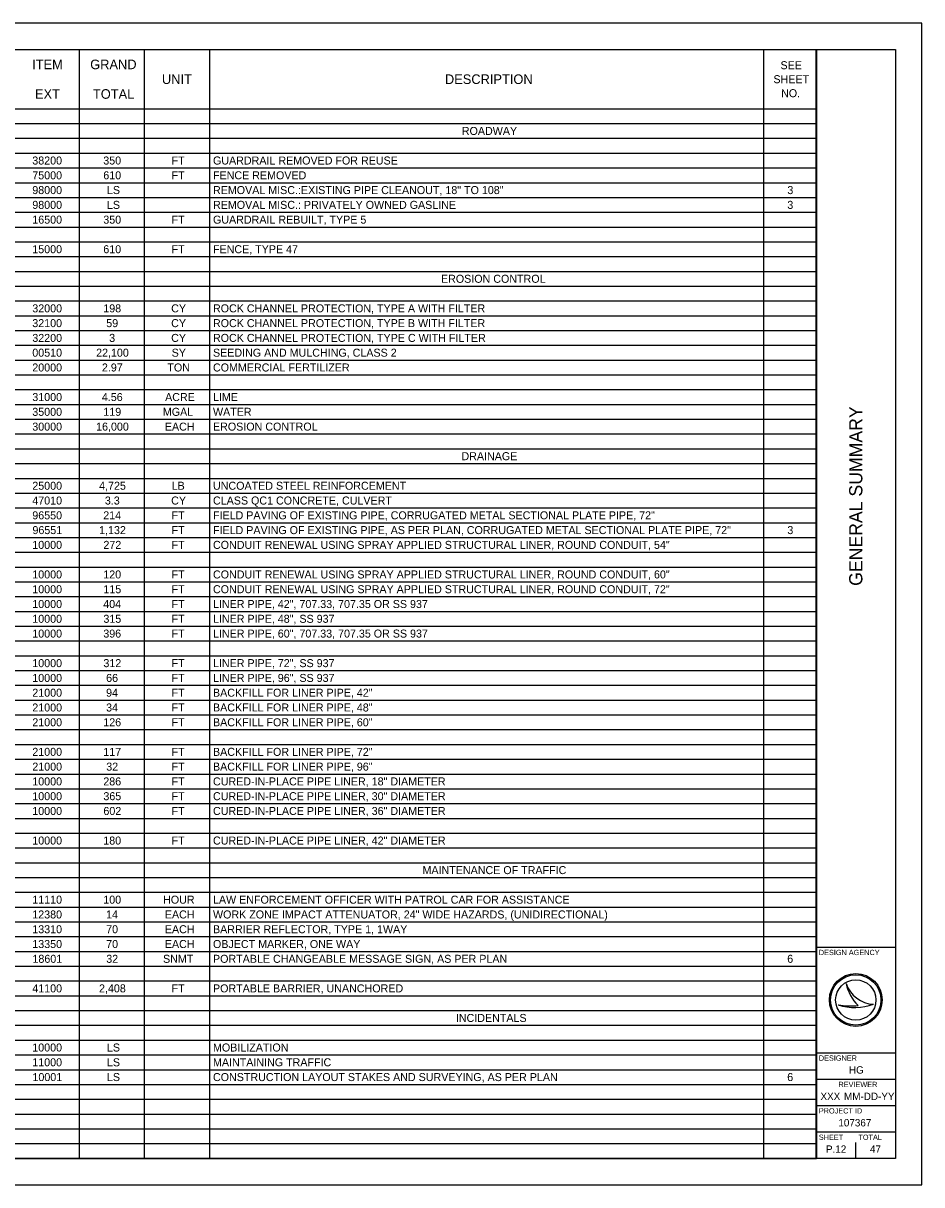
# Model space of a CAD drawing. Extents: x 0 to 34, y 0 to 22.
# Drawn here: x 16.98 to 34, y 0 to 22 of the extents above; entities that cross this region are included whole.
import ezdxf

# ---------------------------------------------------------------- set-up
doc = ezdxf.new("R2010")
doc.units = 0
for name, color, linetype in [('Default', 7, 'Continuous'), ('SH_Border', 7, 'Continuous'), ('SH_Cut_Line', 7, 'Continuous'), ('SH_Data', 7, 'Continuous')]:
    doc.layers.add(name, color=color, linetype=linetype)

msp = doc.modelspace()

# ---------------------------------------------------------------- linework, layer by layer
at = {"layer": 'Default'}
for p, q in [((1.5, 21.5), (32.004, 21.5)), ((18.036, 21.5), (18.036, 0.5)), ((19.272, 21.5), (19.272, 0.5)), ((20.507, 21.5), (20.507, 0.5)), ((30.999, 21.5), (30.999, 0.5)), ((32.004, 21.5), (32.004, 0.5)), ((1.5, 20.38), (32.004, 20.38)), ((1.5, 20.1), (32.004, 20.1)), ((1.5, 19.82), (32.004, 19.82)), ((1.5, 19.54), (32.004, 19.54)), ((1.5, 19.26), (32.004, 19.26)), ((1.5, 18.98), (32.004, 18.98)), ((1.5, 18.7), (32.004, 18.7)), ((1.5, 18.42), (32.004, 18.42)), ((1.5, 18.14), (32.004, 18.14)), ((1.5, 17.86), (32.004, 17.86)), ((1.5, 17.58), (32.004, 17.58)), ((1.5, 17.3), (32.004, 17.3)), ((1.5, 17.02), (32.004, 17.02)), ((1.5, 16.74), (32.004, 16.74)), ((1.5, 16.46), (32.004, 16.46)), ((1.5, 16.18), (32.004, 16.18)), ((1.5, 15.9), (32.004, 15.9)), ((1.5, 15.62), (32.004, 15.62)), ((1.5, 15.34), (32.004, 15.34)), ((1.5, 15.06), (32.004, 15.06)), ((1.5, 14.78), (32.004, 14.78)), ((1.5, 14.5), (32.004, 14.5)), ((1.5, 14.22), (32.004, 14.22)), ((1.5, 13.94), (32.004, 13.94)), ((1.5, 13.66), (32.004, 13.66)), ((1.5, 13.38), (32.004, 13.38)), ((1.5, 13.1), (32.004, 13.1)), ((1.5, 12.82), (32.004, 12.82)), ((1.5, 12.54), (32.004, 12.54)), ((1.5, 12.26), (32.004, 12.26)), ((1.5, 11.98), (32.004, 11.98)), ((1.5, 11.7), (32.004, 11.7)), ((1.5, 11.42), (32.004, 11.42)), ((1.5, 11.14), (32.004, 11.14)), ((1.5, 10.86), (32.004, 10.86)), ((1.5, 10.58), (32.004, 10.58)), ((1.5, 10.3), (32.004, 10.3)), ((1.5, 10.02), (32.004, 10.02)), ((1.5, 9.74), (32.004, 9.74)), ((1.5, 9.46), (32.004, 9.46)), ((1.5, 9.18), (32.004, 9.18)), ((1.5, 8.9), (32.004, 8.9)), ((1.5, 8.62), (32.004, 8.62)), ((1.5, 8.34), (32.004, 8.34)), ((1.5, 8.06), (32.004, 8.06)), ((1.5, 7.78), (32.004, 7.78)), ((1.5, 7.5), (32.004, 7.5)), ((1.5, 7.22), (32.004, 7.22)), ((1.5, 6.94), (32.004, 6.94)), ((1.5, 6.66), (32.004, 6.66)), ((1.5, 6.38), (32.004, 6.38)), ((1.5, 6.1), (32.004, 6.1)), ((1.5, 5.82), (32.004, 5.82)), ((1.5, 5.54), (32.004, 5.54)), ((1.5, 5.26), (32.004, 5.26)), ((1.5, 4.98), (32.004, 4.98)), ((1.5, 4.7), (32.004, 4.7)), ((1.5, 4.42), (32.004, 4.42)), ((1.5, 4.14), (32.004, 4.14)), ((1.5, 3.86), (32.004, 3.86)), ((1.5, 3.58), (32.004, 3.58)), ((1.5, 3.3), (32.004, 3.3)), ((1.5, 3.02), (32.004, 3.02)), ((1.5, 2.74), (32.004, 2.74)), ((1.5, 2.46), (32.004, 2.46)), ((1.5, 2.18), (32.004, 2.18)), ((1.5, 1.9), (32.004, 1.9)), ((1.5, 1.62), (32.004, 1.62)), ((1.5, 1.34), (32.004, 1.34)), ((1.5, 1.06), (32.004, 1.06)), ((1.5, 0.78), (32.004, 0.78)), ((1.5, 0.5), (32.004, 0.5))]:
    msp.add_line(p, q, dxfattribs=at)
at = {"layer": 'SH_Border'}
for p, q in [((32, 0.5), (32, 21.5)), ((32, 4.5), (33.5, 4.5)), ((32, 2.5), (33.5, 2.5)), ((32, 2), (33.5, 2)), ((32, 1.5), (33.5, 1.5)), ((32, 1), (33.5, 1))]:
    msp.add_line(p, q, dxfattribs=at)
msp.add_lwpolyline([(1.5, 21.5), (33.5, 21.5), (33.5, 0.5), (1.5, 0.5)], close=True, dxfattribs=at)
at = {"layer": 'SH_Cut_Line'}
msp.add_lwpolyline([(0, 0), (34, 0), (34, 22), (0, 22)], close=True, dxfattribs=at)
at = {"layer": 'SH_Data'}
for p, q in [((32.567, 3.81), (32.567, 3.81)), ((32.417, 3.41), (32.417, 3.41)), ((32.75, 3.5), (32.75, 3.5)), ((33.087, 3.419), (33.087, 3.419)), ((32.375, 0.675), (32.375, 0.675)), ((32.75, 0.5), (32.75, 0.8))]:
    msp.add_line(p, q, dxfattribs=at)
for radius in [0.5, 0.477, 0.477, 0.382]:
    msp.add_circle((32.75, 3.5), radius, dxfattribs=at)
for centre, radius, start, end in [((33.116, 3.998), 0.58, 198.9257, 198.9319), ((33.347, 3.97), 0.796, 191.6379, 191.6421), ((33.116, 3.998), 0.58, 198.9319, 267.1657), ((33.347, 3.97), 0.796, 191.6421, 226.0947), ((32.739, 4.37), 1.013, 251.4576, 290.0832), ((32.648, 4.654), 1.266, 259.4964, 259.4995), ((32.739, 4.37), 1.013, 251.4527, 251.4576), ((32.648, 4.654), 1.266, 259.4995, 276.6672)]:
    msp.add_arc(centre, radius, start, end, dxfattribs=at)

# ---------------------------------------------------------------- texts
at = {"layer": 'Default'}
for s, height, p in [('ITEM', 0.1818, (17.147, 21.129)), ('GRAND', 0.1818, (18.247, 21.129)), ('SEE ', 0.1515, (31.324, 21.129)), ('UNIT', 0.1818, (19.606, 20.849)), ('DESCRIPTION', 0.18184, (24.967, 20.849)), ('SHEET ', 0.1515, (31.19, 20.864)), ('EXT', 0.1818, (17.201, 20.569)), ('TOTAL', 0.1818, (18.299, 20.569)), ('NO.', 0.1515, (31.335, 20.599)), ('ROADWAY', 0.1515, (25.287, 19.884)), ('38200', 0.1515, (17.15, 19.324)), ('350', 0.1515, (18.495, 19.324)), ('FT', 0.1515, (19.789, 19.324)), ('GUARDRAIL REMOVED FOR REUSE', 0.15153, (20.573, 19.324)), ('75000', 0.1515, (17.15, 19.044)), ('610', 0.1515, (18.495, 19.044)), ('FT', 0.1515, (19.789, 19.044)), ('FENCE REMOVED', 0.15153, (20.573, 19.044)), ('98000', 0.1515, (17.15, 18.764)), ('LS', 0.1515, (18.564, 18.764)), ('REMOVAL MISC.:EXISTING PIPE CLEANOUT, 18" TO 108"', 0.15153, (20.573, 18.764)), ('3', 0.152, (31.453, 18.764)), ('98000', 0.1515, (17.15, 18.484)), ('LS', 0.1515, (18.564, 18.484)), ('REMOVAL MISC.: PRIVATELY OWNED GASLINE', 0.15153, (20.573, 18.484)), ('3', 0.152, (31.453, 18.484)), ('16500', 0.1515, (17.15, 18.204)), ('350', 0.1515, (18.495, 18.204)), ('FT', 0.1515, (19.789, 18.204)), ('GUARDRAIL REBUILT, TYPE 5', 0.15153, (20.573, 18.204)), ('15000', 0.1515, (17.15, 17.644)), ('610', 0.1515, (18.495, 17.644)), ('FT', 0.1515, (19.789, 17.644)), ('FENCE, TYPE 47', 0.15153, (20.573, 17.644)), ('EROSION CONTROL', 0.15153, (24.892, 17.084)), ('32000', 0.1515, (17.15, 16.524)), ('198', 0.1515, (18.495, 16.524)), ('CY', 0.1515, (19.781, 16.524)), ('ROCK CHANNEL PROTECTION, TYPE A WITH FILTER', 0.15153, (20.573, 16.524)), ('32100', 0.1515, (17.15, 16.244)), ('59', 0.1515, (18.551, 16.244)), ('CY', 0.1515, (19.781, 16.244)), ('ROCK CHANNEL PROTECTION, TYPE B WITH FILTER', 0.15153, (20.573, 16.244)), ('32200', 0.1515, (17.15, 15.964)), ('3', 0.152, (18.606, 15.964)), ('CY', 0.1515, (19.781, 15.964)), ('ROCK CHANNEL PROTECTION, TYPE C WITH FILTER', 0.15153, (20.573, 15.964)), ('00510', 0.1515, (17.15, 15.684)), ('22,100', 0.1515, (18.359, 15.684)), ('SY', 0.1515, (19.79, 15.684)), ('SEEDING AND MULCHING, CLASS 2', 0.15153, (20.573, 15.684)), ('20000', 0.1515, (17.15, 15.404)), ('2.97', 0.1515, (18.469, 15.404)), ('TON', 0.1515, (19.709, 15.404)), ('COMMERCIAL FERTILIZER', 0.15153, (20.573, 15.404)), ('31000', 0.1515, (17.15, 14.844)), ('4.56', 0.1515, (18.468, 14.844)), ('ACRE', 0.1515, (19.666, 14.844)), ('LIME', 0.1515, (20.573, 14.844)), ('35000', 0.1515, (17.15, 14.564)), ('119', 0.1515, (18.496, 14.564)), ('MGAL', 0.1515, (19.623, 14.564)), ('WATER', 0.1515, (20.573, 14.564)), ('30000', 0.1515, (17.15, 14.284)), ('16,000', 0.1515, (18.359, 14.284)), ('EACH', 0.1515, (19.661, 14.284)), ('EROSION CONTROL', 0.15153, (20.573, 14.284)), ('DRAINAGE', 0.1515, (25.28, 13.724)), ('25000', 0.1515, (17.15, 13.164)), ('4,725', 0.1515, (18.416, 13.164)), ('LB', 0.1515, (19.79, 13.164)), ('UNCOATED STEEL REINFORCEMENT', 0.15153, (20.573, 13.164)), ('47010', 0.1515, (17.15, 12.884)), ('3.3', 0.1515, (18.525, 12.884)), ('CY', 0.1515, (19.781, 12.884)), ('CLASS QC1 CONCRETE, CULVERT', 0.15153, (20.573, 12.884)), ('96550', 0.1515, (17.15, 12.604)), ('214', 0.1515, (18.494, 12.604)), ('FT', 0.1515, (19.789, 12.604)), ('FIELD PAVING OF EXISTING PIPE, CORRUGATED METAL SECTIONAL PLATE PIPE, 72"', 0.15153, (20.573, 12.604)), ('96551', 0.1515, (17.153, 12.324)), ('1,132', 0.1515, (18.416, 12.324)), ('FT', 0.1515, (19.789, 12.324)), ('FIELD PAVING OF EXISTING PIPE, AS PER PLAN, CORRUGATED METAL SECTIONAL PLATE PIPE, 72"', 0.15153, (20.573, 12.324)), ('3', 0.152, (31.453, 12.324)), ('10000', 0.1515, (17.15, 12.044)), ('272', 0.1515, (18.497, 12.044)), ('FT', 0.1515, (19.789, 12.044)), ('CONDUIT RENEWAL USING SPRAY APPLIED STRUCTURAL LINER, ROUND CONDUIT, 54"', 0.15153, (20.573, 12.044)), ('10000', 0.1515, (17.15, 11.484)), ('120', 0.1515, (18.495, 11.484)), ('FT', 0.1515, (19.789, 11.484)), ('CONDUIT RENEWAL USING SPRAY APPLIED STRUCTURAL LINER, ROUND CONDUIT, 60"', 0.15153, (20.573, 11.484)), ('10000', 0.1515, (17.15, 11.204)), ('115', 0.1515, (18.497, 11.204)), ('FT', 0.1515, (19.789, 11.204)), ('CONDUIT RENEWAL USING SPRAY APPLIED STRUCTURAL LINER, ROUND CONDUIT, 72"', 0.15153, (20.573, 11.204)), ('10000', 0.1515, (17.15, 10.924)), ('404', 0.1515, (18.494, 10.924)), ('FT', 0.1515, (19.789, 10.924)), ('LINER PIPE, 42", 707.33, 707.35 OR SS 937', 0.15153, (20.573, 10.924)), ('10000', 0.1515, (17.15, 10.644)), ('315', 0.1515, (18.497, 10.644)), ('FT', 0.1515, (19.789, 10.644)), ('LINER PIPE, 48", SS 937', 0.15153, (20.573, 10.644)), ('10000', 0.1515, (17.15, 10.364)), ('396', 0.1515, (18.495, 10.364)), ('FT', 0.1515, (19.789, 10.364)), ('LINER PIPE, 60", 707.33, 707.35 OR SS 937', 0.15153, (20.573, 10.364)), ('10000', 0.1515, (17.15, 9.804)), ('312', 0.1515, (18.497, 9.804)), ('FT', 0.1515, (19.789, 9.804)), ('LINER PIPE, 72", SS 937', 0.15153, (20.573, 9.804)), ('10000', 0.1515, (17.15, 9.524)), ('66', 0.1515, (18.549, 9.524)), ('FT', 0.1515, (19.789, 9.524)), ('LINER PIPE, 96", SS 937', 0.15153, (20.573, 9.524)), ('21000', 0.1515, (17.15, 9.244)), ('94', 0.1515, (18.548, 9.244)), ('FT', 0.1515, (19.789, 9.244)), ('BACKFILL FOR LINER PIPE, 42"', 0.15153, (20.573, 9.244)), ('21000', 0.1515, (17.15, 8.964)), ('34', 0.1515, (18.548, 8.964)), ('FT', 0.1515, (19.789, 8.964)), ('BACKFILL FOR LINER PIPE, 48"', 0.15153, (20.573, 8.964)), ('21000', 0.1515, (17.15, 8.684)), ('126', 0.1515, (18.495, 8.684)), ('FT', 0.1515, (19.789, 8.684)), ('BACKFILL FOR LINER PIPE, 60"', 0.15153, (20.573, 8.684)), ('21000', 0.1515, (17.15, 8.124)), ('117', 0.1515, (18.496, 8.124)), ('FT', 0.1515, (19.789, 8.124)), ('BACKFILL FOR LINER PIPE, 72"', 0.15153, (20.573, 8.124)), ('21000', 0.1515, (17.15, 7.844)), ('32', 0.1515, (18.551, 7.844)), ('FT', 0.1515, (19.789, 7.844)), ('BACKFILL FOR LINER PIPE, 96"', 0.15153, (20.573, 7.844)), ('10000', 0.1515, (17.15, 7.564)), ('286', 0.1515, (18.495, 7.564)), ('FT', 0.1515, (19.789, 7.564)), ('CURED-IN-PLACE PIPE LINER, 18" DIAMETER', 0.15153, (20.573, 7.564)), ('10000', 0.1515, (17.15, 7.284)), ('365', 0.1515, (18.497, 7.284)), ('FT', 0.1515, (19.789, 7.284)), ('CURED-IN-PLACE PIPE LINER, 30" DIAMETER', 0.15153, (20.573, 7.284)), ('10000', 0.1515, (17.15, 7.004)), ('602', 0.1515, (18.497, 7.004)), ('FT', 0.1515, (19.789, 7.004)), ('CURED-IN-PLACE PIPE LINER, 36" DIAMETER', 0.15153, (20.573, 7.004)), ('10000', 0.1515, (17.15, 6.444)), ('180', 0.1515, (18.495, 6.444)), ('FT', 0.1515, (19.789, 6.444)), ('CURED-IN-PLACE PIPE LINER, 42" DIAMETER', 0.15153, (20.573, 6.444)), ('MAINTENANCE OF TRAFFIC', 0.15153, (24.542, 5.884)), ('11110', 0.1515, (17.15, 5.324)), ('100', 0.1515, (18.495, 5.324)), ('HOUR', 0.1515, (19.628, 5.324)), ('LAW ENFORCEMENT OFFICER WITH PATROL CAR FOR ASSISTANCE', 0.15153, (20.573, 5.324)), ('12380', 0.1515, (17.15, 5.044)), ('14', 0.1515, (18.548, 5.044)), ('EACH', 0.1515, (19.661, 5.044)), ('WORK ZONE IMPACT ATTENUATOR, 24" WIDE HAZARDS, (UNIDIRECTIONAL)', 0.15153, (20.573, 5.044)), ('13310', 0.1515, (17.15, 4.764)), ('70', 0.1515, (18.549, 4.764)), ('EACH', 0.1515, (19.661, 4.764)), ('BARRIER REFLECTOR, TYPE 1, 1WAY', 0.15153, (20.573, 4.764)), ('13350', 0.1515, (17.15, 4.484)), ('70', 0.1515, (18.549, 4.484)), ('EACH', 0.1515, (19.661, 4.484)), ('OBJECT MARKER, ONE WAY', 0.15153, (20.573, 4.484)), ('18601', 0.1515, (17.153, 4.204)), ('32', 0.1515, (18.551, 4.204)), ('SNMT', 0.1515, (19.627, 4.204)), ('PORTABLE CHANGEABLE MESSAGE SIGN, AS PER PLAN', 0.15153, (20.573, 4.204)), ('6', 0.152, (31.451, 4.204)), ('41100', 0.1515, (17.15, 3.644)), ('2,408', 0.1515, (18.414, 3.644)), ('FT', 0.1515, (19.789, 3.644)), ('PORTABLE BARRIER, UNANCHORED', 0.15153, (20.573, 3.644)), ('INCIDENTALS', 0.15153, (25.174, 3.084)), ('10000', 0.1515, (17.15, 2.524)), ('LS', 0.1515, (18.564, 2.524)), ('MOBILIZATION', 0.15153, (20.573, 2.524)), ('11000', 0.1515, (17.15, 2.244)), ('LS', 0.1515, (18.564, 2.244)), ('MAINTAINING TRAFFIC', 0.15153, (20.573, 2.244)), ('10001', 0.1515, (17.153, 1.964)), ('LS', 0.1515, (18.564, 1.964)), ('CONSTRUCTION LAYOUT STAKES AND SURVEYING, AS PER PLAN', 0.15153, (20.573, 1.964)), ('6', 0.152, (31.451, 1.964))]:
    msp.add_text(s, height=height, dxfattribs=at).set_placement(p)
at = {"layer": 'SH_Data'}
msp.add_text('GENERAL SUMMARY', height=0.25, rotation=90, dxfattribs=at).set_placement((32.875, 11.344))
for s, height, p in [('DESIGN AGENCY', 0.1, (32.05, 4.35)), ('DESIGNER', 0.1, (32.05, 2.35)), ('HG', 0.14, (32.62, 2.105)), ('REVIEWER', 0.1, (32.422, 1.85)), ('XXX', 0.14, (32.081, 1.605)), ('MM-DD-YY', 0.14, (32.527, 1.605)), ('PROJECT ID', 0.1, (32.05, 1.35)), ('107367', 0.14, (32.42, 1.105)), ('SHEET', 0.1, (32.05, 0.85)), ('TOTAL', 0.1, (32.8, 0.85)), ('P.12', 0.14, (32.185, 0.605)), ('47', 0.14, (33.018, 0.605))]:
    msp.add_text(s, height=height, dxfattribs=at).set_placement(p)

doc.saveas('drawing.dxf')
